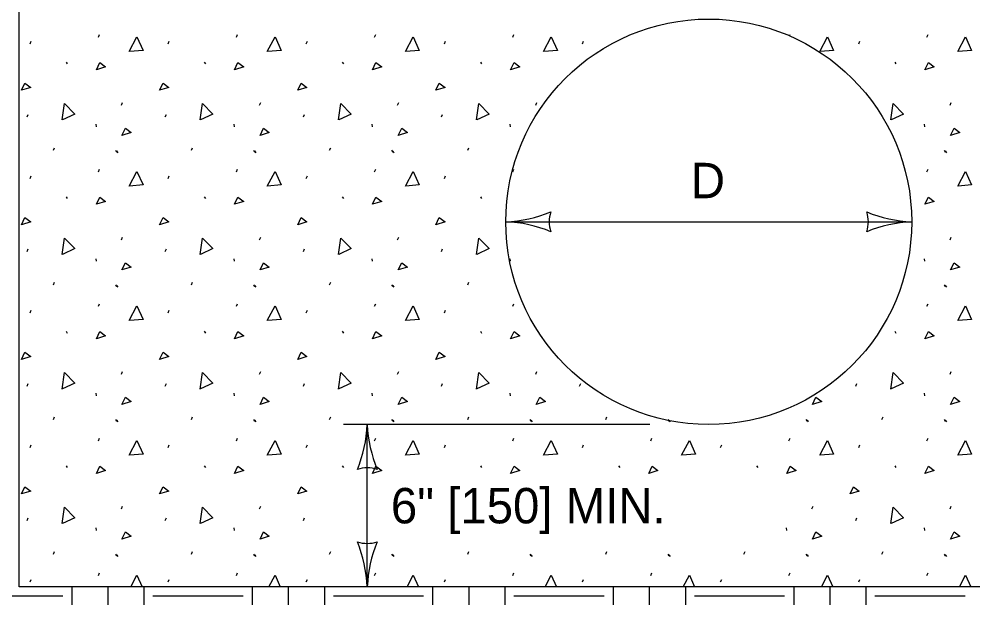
# Model space of a CAD drawing. Extents: x 49991.4 to 50061.4, y 49960.6 to 50011.4.
# Drawn here: x 50012.414 to 50014.03, y 49995.549 to 49996.543 of the extents above; entities that cross this region are included whole.
import ezdxf

# ---------------------------------------------------------------- set-up
doc = ezdxf.new("R2010")
doc.units = 0
for name, color, linetype in [('Level 1', 7, 'Continuous'), ('Level 2', 7, 'Continuous'), ('Level 3', 7, 'Continuous')]:
    doc.layers.add(name, color=color, linetype=linetype)

msp = doc.modelspace()

# ---------------------------------------------------------------- linework, layer by layer
at = {"layer": 'Level 1'}
for p, q in [((50012.4143, 49995.58), (50012.4143, 49997.0926)), ((50012.5487, 49996.5119), (50012.5506, 49996.5163)), ((50012.7826, 49996.5119), (50012.7846, 49996.5163)), ((50013.0166, 49996.5119), (50013.0186, 49996.5163)), ((50013.2506, 49996.5119), (50013.2525, 49996.5163)), ((50013.7194, 49996.514), (50013.7204, 49996.5163)), ((50013.9524, 49996.5119), (50013.9544, 49996.5163)), ((50012.4329, 49996.5007), (50012.4349, 49996.5051)), ((50012.6669, 49996.5007), (50012.6688, 49996.5051)), ((50012.9008, 49996.5007), (50012.9028, 49996.5051)), ((50013.1348, 49996.5007), (50013.1368, 49996.5051)), ((50013.3688, 49996.5007), (50013.3707, 49996.5051)), ((50013.8367, 49996.5007), (50013.8386, 49996.5051)), ((50012.494, 49996.4694), (50012.4959, 49996.4665)), ((50012.7279, 49996.4694), (50012.7299, 49996.4665)), ((50012.9619, 49996.4694), (50012.9639, 49996.4665)), ((50013.1959, 49996.4694), (50013.1978, 49996.4665)), ((50013.8977, 49996.4694), (50013.8997, 49996.4665)), ((50012.5878, 49996.3967), (50012.5897, 49996.4011)), ((50012.8217, 49996.3967), (50012.8237, 49996.4011)), ((50013.0557, 49996.3967), (50013.0576, 49996.4011)), ((50013.2896, 49996.3967), (50013.2916, 49996.4011)), ((50013.9915, 49996.3967), (50013.9935, 49996.4011)), ((50012.4281, 49996.3766), (50012.43, 49996.381)), ((50012.662, 49996.3766), (50012.664, 49996.381)), ((50012.896, 49996.3766), (50012.8979, 49996.381)), ((50013.1299, 49996.3766), (50013.1319, 49996.381)), ((50012.5442, 49996.3644), (50012.5447, 49996.36)), ((50012.7781, 49996.3644), (50012.7786, 49996.36)), ((50013.0121, 49996.3644), (50013.0126, 49996.36)), ((50013.246, 49996.3644), (50013.2465, 49996.36)), ((50013.9479, 49996.3644), (50013.9484, 49996.36)), ((50012.4725, 49996.32), (50012.4744, 49996.3244)), ((50012.7065, 49996.32), (50012.7084, 49996.3244)), ((50012.9404, 49996.32), (50012.9424, 49996.3244)), ((50013.1744, 49996.32), (50013.1763, 49996.3244)), ((50012.5775, 49996.32), (50012.5795, 49996.317)), ((50012.5795, 49996.3189), (50012.5814, 49996.3159)), ((50012.8115, 49996.32), (50012.8134, 49996.317)), ((50012.8134, 49996.3189), (50012.8154, 49996.3159)), ((50013.0454, 49996.32), (50013.0474, 49996.317)), ((50013.0474, 49996.3189), (50013.0493, 49996.3159)), ((50013.9813, 49996.32), (50013.9832, 49996.317)), ((50013.9832, 49996.3189), (50013.9852, 49996.3159)), ((50012.4329, 49996.2725), (50012.4349, 49996.2769)), ((50012.5487, 49996.2838), (50012.5506, 49996.2882)), ((50012.6669, 49996.2725), (50012.6688, 49996.2769)), ((50012.7826, 49996.2838), (50012.7846, 49996.2882)), ((50012.9008, 49996.2725), (50012.9028, 49996.2769)), ((50013.0166, 49996.2838), (50013.0186, 49996.2882)), ((50013.1348, 49996.2725), (50013.1368, 49996.2769)), ((50013.2506, 49996.2838), (50013.2525, 49996.2882)), ((50013.9524, 49996.2838), (50013.9544, 49996.2882)), ((50012.494, 49996.2413), (50012.4959, 49996.2384)), ((50012.7279, 49996.2413), (50012.7299, 49996.2384)), ((50012.9619, 49996.2413), (50012.9639, 49996.2384)), ((50013.1959, 49996.2413), (50013.1978, 49996.2384)), ((50012.5878, 49996.1685), (50012.5897, 49996.1729)), ((50012.8217, 49996.1685), (50012.8237, 49996.1729)), ((50013.0557, 49996.1685), (50013.0576, 49996.1729)), ((50013.9915, 49996.1685), (50013.9935, 49996.1729)), ((50012.4281, 49996.1485), (50012.43, 49996.1529)), ((50012.662, 49996.1485), (50012.664, 49996.1529)), ((50012.896, 49996.1485), (50012.8979, 49996.1529)), ((50013.1299, 49996.1485), (50013.1319, 49996.1529)), ((50012.5442, 49996.1362), (50012.5447, 49996.1318)), ((50012.7781, 49996.1362), (50012.7786, 49996.1318)), ((50013.0121, 49996.1362), (50013.0126, 49996.1318)), ((50013.246, 49996.1362), (50013.2465, 49996.1318)), ((50013.9479, 49996.1362), (50013.9484, 49996.1318)), ((50012.4725, 49996.0918), (50012.4744, 49996.0962)), ((50012.7065, 49996.0918), (50012.7084, 49996.0962)), ((50012.9404, 49996.0918), (50012.9424, 49996.0962)), ((50013.1744, 49996.0918), (50013.1763, 49996.0962)), ((50012.5775, 49996.0918), (50012.5795, 49996.0889)), ((50012.5795, 49996.0907), (50012.5814, 49996.0878)), ((50012.8115, 49996.0918), (50012.8134, 49996.0889)), ((50012.8134, 49996.0907), (50012.8154, 49996.0878)), ((50013.0454, 49996.0918), (50013.0474, 49996.0889)), ((50013.0474, 49996.0907), (50013.0493, 49996.0878)), ((50013.9813, 49996.0918), (50013.9832, 49996.0889)), ((50013.9832, 49996.0907), (50013.9852, 49996.0878)), ((50012.4329, 49996.0444), (50012.4349, 49996.0488)), ((50012.5487, 49996.0556), (50012.5506, 49996.06)), ((50012.6669, 49996.0444), (50012.6688, 49996.0488)), ((50012.7826, 49996.0556), (50012.7846, 49996.06)), ((50012.9008, 49996.0444), (50012.9028, 49996.0488)), ((50013.0166, 49996.0556), (50013.0186, 49996.06)), ((50013.1348, 49996.0444), (50013.1368, 49996.0488)), ((50013.2506, 49996.0556), (50013.2525, 49996.06)), ((50013.9524, 49996.0556), (50013.9544, 49996.06)), ((50012.494, 49996.0131), (50012.4959, 49996.0102)), ((50012.7279, 49996.0131), (50012.7299, 49996.0102)), ((50012.9619, 49996.0131), (50012.9639, 49996.0102)), ((50013.1959, 49996.0131), (50013.1978, 49996.0102)), ((50013.8977, 49996.0131), (50013.8997, 49996.0102)), ((50012.5878, 49995.9404), (50012.5897, 49995.9448)), ((50012.8217, 49995.9404), (50012.8237, 49995.9448)), ((50013.0557, 49995.9404), (50013.0576, 49995.9448)), ((50013.2896, 49995.9404), (50013.2916, 49995.9448)), ((50013.9915, 49995.9404), (50013.9935, 49995.9448)), ((50012.4281, 49995.9203), (50012.43, 49995.9247)), ((50012.662, 49995.9203), (50012.664, 49995.9247)), ((50012.896, 49995.9203), (50012.8979, 49995.9247)), ((50013.1299, 49995.9203), (50013.1319, 49995.9247)), ((50013.3639, 49995.9203), (50013.3658, 49995.9247)), ((50013.8318, 49995.9203), (50013.8337, 49995.9247)), ((50012.5442, 49995.9081), (50012.5447, 49995.9037)), ((50012.7781, 49995.9081), (50012.7786, 49995.9037)), ((50013.0121, 49995.9081), (50013.0126, 49995.9037)), ((50013.246, 49995.9081), (50013.2465, 49995.9037)), ((50013.9479, 49995.9081), (50013.9484, 49995.9037)), ((50012.4725, 49995.8637), (50012.4744, 49995.8681)), ((50012.5775, 49995.8637), (50012.5795, 49995.8608)), ((50012.5795, 49995.8626), (50012.5814, 49995.8596)), ((50012.7065, 49995.8637), (50012.7084, 49995.8681)), ((50012.8115, 49995.8637), (50012.8134, 49995.8608)), ((50012.8134, 49995.8626), (50012.8154, 49995.8596)), ((50012.9404, 49995.8637), (50012.9424, 49995.8681)), ((50013.0454, 49995.8637), (50013.0474, 49995.8608)), ((50013.0474, 49995.8626), (50013.0493, 49995.8596)), ((50013.1744, 49995.8637), (50013.1763, 49995.8681)), ((50013.2794, 49995.8637), (50013.2813, 49995.8608)), ((50013.2813, 49995.8626), (50013.2833, 49995.8596)), ((50013.4083, 49995.8637), (50013.4103, 49995.8681)), ((50013.5133, 49995.8637), (50013.5153, 49995.8608)), ((50013.5153, 49995.8626), (50013.5172, 49995.8596)), ((50013.7473, 49995.8637), (50013.7493, 49995.8608)), ((50013.7493, 49995.8626), (50013.7512, 49995.8596)), ((50013.8762, 49995.8637), (50013.8782, 49995.8681)), ((50013.9813, 49995.8637), (50013.9832, 49995.8608)), ((50013.9832, 49995.8626), (50013.9852, 49995.8596)), ((50012.4329, 49995.8162), (50012.4349, 49995.8206)), ((50012.5487, 49995.8275), (50012.5506, 49995.8319)), ((50012.6669, 49995.8162), (50012.6688, 49995.8206)), ((50012.7826, 49995.8275), (50012.7846, 49995.8319)), ((50012.9008, 49995.8162), (50012.9028, 49995.8206)), ((50013.0166, 49995.8275), (50013.0186, 49995.8319)), ((50013.1348, 49995.8162), (50013.1368, 49995.8206)), ((50013.2506, 49995.8275), (50013.2525, 49995.8319)), ((50013.3688, 49995.8162), (50013.3707, 49995.8206)), ((50013.4845, 49995.8275), (50013.4865, 49995.8319)), ((50013.6027, 49995.8162), (50013.6047, 49995.8206)), ((50013.7185, 49995.8275), (50013.7204, 49995.8319)), ((50013.8367, 49995.8162), (50013.8386, 49995.8206)), ((50013.9524, 49995.8275), (50013.9544, 49995.8319)), ((50012.494, 49995.785), (50012.4959, 49995.7821)), ((50012.7279, 49995.785), (50012.7299, 49995.7821)), ((50012.9619, 49995.785), (50012.9639, 49995.7821)), ((50013.1959, 49995.785), (50013.1978, 49995.7821)), ((50013.4298, 49995.785), (50013.4318, 49995.7821)), ((50013.6638, 49995.785), (50013.6657, 49995.7821)), ((50013.8977, 49995.785), (50013.8997, 49995.7821)), ((50012.5878, 49995.7122), (50012.5897, 49995.7166)), ((50012.8217, 49995.7122), (50012.8237, 49995.7166)), ((50013.7576, 49995.7122), (50013.7595, 49995.7166)), ((50013.9915, 49995.7122), (50013.9935, 49995.7166)), ((50012.4281, 49995.6922), (50012.43, 49995.6966)), ((50012.662, 49995.6922), (50012.664, 49995.6966)), ((50012.896, 49995.6922), (50012.8979, 49995.6966)), ((50013.8318, 49995.6922), (50013.8337, 49995.6966)), ((50012.5442, 49995.6799), (50012.5447, 49995.6755)), ((50012.7781, 49995.6799), (50012.7786, 49995.6755)), ((50013.714, 49995.6799), (50013.7144, 49995.6755)), ((50013.9479, 49995.6799), (50013.9484, 49995.6755)), ((50012.4725, 49995.6355), (50012.4744, 49995.6399)), ((50012.5775, 49995.6355), (50012.5795, 49995.6326)), ((50012.5795, 49995.6344), (50012.5814, 49995.6315)), ((50012.7065, 49995.6355), (50012.7084, 49995.6399)), ((50012.8115, 49995.6355), (50012.8134, 49995.6326)), ((50012.8134, 49995.6344), (50012.8154, 49995.6315)), ((50012.9404, 49995.6355), (50012.9424, 49995.6399)), ((50013.0454, 49995.6355), (50013.0474, 49995.6326)), ((50013.0474, 49995.6344), (50013.0493, 49995.6315)), ((50013.1744, 49995.6355), (50013.1763, 49995.6399)), ((50013.2794, 49995.6355), (50013.2813, 49995.6326)), ((50013.2813, 49995.6344), (50013.2833, 49995.6315)), ((50013.4083, 49995.6355), (50013.4103, 49995.6399)), ((50013.5133, 49995.6355), (50013.5153, 49995.6326)), ((50013.5153, 49995.6344), (50013.5172, 49995.6315)), ((50013.6423, 49995.6355), (50013.6442, 49995.6399)), ((50013.7473, 49995.6355), (50013.7493, 49995.6326)), ((50013.7493, 49995.6344), (50013.7512, 49995.6315)), ((50013.8762, 49995.6355), (50013.8782, 49995.6399)), ((50013.9813, 49995.6355), (50013.9832, 49995.6326)), ((50013.9832, 49995.6344), (50013.9852, 49995.6315)), ((50012.5487, 49995.5993), (50012.5506, 49995.6037)), ((50012.7826, 49995.5993), (50012.7846, 49995.6037)), ((50013.0166, 49995.5993), (50013.0186, 49995.6037)), ((50013.2506, 49995.5993), (50013.2525, 49995.6037)), ((50013.4845, 49995.5993), (50013.4865, 49995.6037)), ((50013.7185, 49995.5993), (50013.7204, 49995.6037)), ((50013.9524, 49995.5993), (50013.9544, 49995.6037)), ((50014.7511, 49995.58), (50012.4143, 49995.58)), ((50012.4329, 49995.5881), (50012.4349, 49995.5925)), ((50012.5035, 49995.58), (50012.5035, 49995.5492)), ((50012.5647, 49995.58), (50012.5647, 49995.5492)), ((50012.6258, 49995.58), (50012.6258, 49995.5492)), ((50012.6669, 49995.5881), (50012.6688, 49995.5925)), ((50012.8093, 49995.58), (50012.8093, 49995.5492)), ((50012.8704, 49995.58), (50012.8704, 49995.5492)), ((50012.9008, 49995.5881), (50012.9028, 49995.5925)), ((50012.9316, 49995.58), (50012.9316, 49995.5492)), ((50013.5484, 49995.58), (50012.9699, 49995.58)), ((50013.115, 49995.58), (50013.115, 49995.5492)), ((50013.1348, 49995.5881), (50013.1368, 49995.5925)), ((50013.1762, 49995.58), (50013.1762, 49995.5492)), ((50013.2373, 49995.58), (50013.2373, 49995.5492)), ((50013.3688, 49995.5881), (50013.3707, 49995.5925)), ((50013.4208, 49995.58), (50013.4208, 49995.5492)), ((50013.482, 49995.58), (50013.482, 49995.5492)), ((50013.5431, 49995.58), (50013.5431, 49995.5492)), ((50013.6027, 49995.5881), (50013.6047, 49995.5925)), ((50013.7266, 49995.58), (50013.7266, 49995.5492)), ((50013.7877, 49995.58), (50013.7877, 49995.5492)), ((50013.8367, 49995.5881), (50013.8386, 49995.5925)), ((50013.8489, 49995.58), (50013.8489, 49995.5492)), ((50012.3353, 49995.5645), (50012.4882, 49995.5645)), ((50012.6411, 49995.5645), (50012.794, 49995.5645)), ((50012.9469, 49995.5645), (50013.0997, 49995.5645)), ((50013.2526, 49995.5645), (50013.4055, 49995.5645)), ((50013.5584, 49995.5645), (50013.7113, 49995.5645)), ((50013.8642, 49995.5645), (50014.017, 49995.5645))]:
    msp.add_line(p, q, dxfattribs=at)
for points in [[(50012.601, 49996.4875), (50012.6141, 49996.5124), (50012.6244, 49996.4895), (50012.6014, 49996.4875)], [(50012.8349, 49996.4875), (50012.8481, 49996.5124), (50012.8584, 49996.4895), (50012.8354, 49996.4875)], [(50013.0689, 49996.4875), (50013.0821, 49996.5124), (50013.0923, 49996.4895), (50013.0694, 49996.4875)], [(50013.3028, 49996.4875), (50013.316, 49996.5124), (50013.3263, 49996.4895), (50013.3033, 49996.4875)], [(50013.7707, 49996.4875), (50013.7839, 49996.5124), (50013.7942, 49996.4895), (50013.7712, 49996.4875)], [(50014.0047, 49996.4875), (50014.0179, 49996.5124), (50014.0281, 49996.4895), (50014.0052, 49996.4875)], [(50012.5453, 49996.4567), (50012.5511, 49996.4689), (50012.5609, 49996.4616), (50012.5453, 49996.4567)], [(50012.7792, 49996.4567), (50012.7851, 49996.4689), (50012.7949, 49996.4616), (50012.7792, 49996.4567)], [(50013.0132, 49996.4567), (50013.019, 49996.4689), (50013.0288, 49996.4616), (50013.0132, 49996.4567)], [(50013.2471, 49996.4567), (50013.253, 49996.4689), (50013.2628, 49996.4616), (50013.2471, 49996.4567)], [(50013.949, 49996.4567), (50013.9549, 49996.4689), (50013.9646, 49996.4616), (50013.949, 49996.4567)], [(50012.4184, 49996.4218), (50012.4242, 49996.434), (50012.434, 49996.4267), (50012.4184, 49996.4218)], [(50012.6523, 49996.4218), (50012.6582, 49996.434), (50012.668, 49996.4267), (50012.6523, 49996.4218)], [(50012.8863, 49996.4218), (50012.8922, 49996.434), (50012.9019, 49996.4267), (50012.8863, 49996.4218)], [(50013.1203, 49996.4218), (50013.1261, 49996.434), (50013.1359, 49996.4267), (50013.1203, 49996.4218)], [(50012.4875, 49996.3716), (50012.4913, 49996.3995), (50012.5088, 49996.3814), (50012.4879, 49996.3717)], [(50012.7214, 49996.3716), (50012.7253, 49996.3995), (50012.7428, 49996.3814), (50012.7219, 49996.3717)], [(50012.9554, 49996.3716), (50012.9593, 49996.3995), (50012.9767, 49996.3814), (50012.9558, 49996.3717)], [(50013.1893, 49996.3716), (50013.1932, 49996.3995), (50013.2107, 49996.3814), (50013.1898, 49996.3717)], [(50013.8912, 49996.3716), (50013.8951, 49996.3995), (50013.9126, 49996.3814), (50013.8917, 49996.3717)], [(50012.5887, 49996.3454), (50012.5946, 49996.3576), (50012.6044, 49996.3503), (50012.5887, 49996.3454)], [(50012.8227, 49996.3454), (50012.8286, 49996.3576), (50012.8383, 49996.3503), (50012.8227, 49996.3454)], [(50013.0567, 49996.3454), (50013.0625, 49996.3576), (50013.0723, 49996.3503), (50013.0567, 49996.3454)], [(50013.9925, 49996.3454), (50013.9984, 49996.3576), (50014.0081, 49996.3503), (50013.9925, 49996.3454)], [(50012.601, 49996.2594), (50012.6141, 49996.2843), (50012.6244, 49996.2613), (50012.6014, 49996.2594)], [(50012.8349, 49996.2594), (50012.8481, 49996.2843), (50012.8584, 49996.2613), (50012.8354, 49996.2594)], [(50013.0689, 49996.2594), (50013.0821, 49996.2843), (50013.0923, 49996.2613), (50013.0694, 49996.2594)], [(50014.0047, 49996.2594), (50014.0179, 49996.2843), (50014.0281, 49996.2613), (50014.0052, 49996.2594)], [(50012.5453, 49996.2286), (50012.5511, 49996.2408), (50012.5609, 49996.2335), (50012.5453, 49996.2286)], [(50012.7792, 49996.2286), (50012.7851, 49996.2408), (50012.7949, 49996.2335), (50012.7792, 49996.2286)], [(50013.0132, 49996.2286), (50013.019, 49996.2408), (50013.0288, 49996.2335), (50013.0132, 49996.2286)], [(50013.949, 49996.2286), (50013.9549, 49996.2408), (50013.9646, 49996.2335), (50013.949, 49996.2286)], [(50012.4184, 49996.1937), (50012.4242, 49996.2059), (50012.434, 49996.1986), (50012.4184, 49996.1937)], [(50012.6523, 49996.1937), (50012.6582, 49996.2059), (50012.668, 49996.1986), (50012.6523, 49996.1937)], [(50012.8863, 49996.1937), (50012.8922, 49996.2059), (50012.9019, 49996.1986), (50012.8863, 49996.1937)], [(50013.1203, 49996.1937), (50013.1261, 49996.2059), (50013.1359, 49996.1986), (50013.1203, 49996.1937)], [(50012.4875, 49996.1434), (50012.4913, 49996.1713), (50012.5088, 49996.1533), (50012.4879, 49996.1436)], [(50012.7214, 49996.1434), (50012.7253, 49996.1713), (50012.7428, 49996.1533), (50012.7219, 49996.1436)], [(50012.9554, 49996.1434), (50012.9593, 49996.1713), (50012.9767, 49996.1533), (50012.9558, 49996.1436)], [(50013.1893, 49996.1434), (50013.1932, 49996.1713), (50013.2107, 49996.1533), (50013.1898, 49996.1436)], [(50012.5887, 49996.1172), (50012.5946, 49996.1294), (50012.6044, 49996.1221), (50012.5887, 49996.1172)], [(50012.8227, 49996.1172), (50012.8286, 49996.1294), (50012.8383, 49996.1221), (50012.8227, 49996.1172)], [(50013.0567, 49996.1172), (50013.0625, 49996.1294), (50013.0723, 49996.1221), (50013.0567, 49996.1172)], [(50013.9925, 49996.1172), (50013.9984, 49996.1294), (50014.0081, 49996.1221), (50013.9925, 49996.1172)], [(50012.601, 49996.0312), (50012.6141, 49996.0561), (50012.6244, 49996.0332), (50012.6014, 49996.0312)], [(50012.8349, 49996.0312), (50012.8481, 49996.0561), (50012.8584, 49996.0332), (50012.8354, 49996.0312)], [(50013.0689, 49996.0312), (50013.0821, 49996.0561), (50013.0923, 49996.0332), (50013.0694, 49996.0312)], [(50014.0047, 49996.0312), (50014.0179, 49996.0561), (50014.0281, 49996.0332), (50014.0052, 49996.0312)], [(50012.5453, 49996.0004), (50012.5511, 49996.0126), (50012.5609, 49996.0053), (50012.5453, 49996.0004)], [(50012.7792, 49996.0004), (50012.7851, 49996.0126), (50012.7949, 49996.0053), (50012.7792, 49996.0004)], [(50013.0132, 49996.0004), (50013.019, 49996.0126), (50013.0288, 49996.0053), (50013.0132, 49996.0004)], [(50013.2471, 49996.0004), (50013.253, 49996.0126), (50013.2628, 49996.0053), (50013.2471, 49996.0004)], [(50013.949, 49996.0004), (50013.9549, 49996.0126), (50013.9646, 49996.0053), (50013.949, 49996.0004)], [(50012.4184, 49995.9655), (50012.4242, 49995.9777), (50012.434, 49995.9704), (50012.4184, 49995.9655)], [(50012.6523, 49995.9655), (50012.6582, 49995.9777), (50012.668, 49995.9704), (50012.6523, 49995.9655)], [(50012.8863, 49995.9655), (50012.8922, 49995.9777), (50012.9019, 49995.9704), (50012.8863, 49995.9655)], [(50013.1203, 49995.9655), (50013.1261, 49995.9777), (50013.1359, 49995.9704), (50013.1203, 49995.9655)], [(50013.8378, 49995.9704), (50013.8374, 49995.9703)], [(50012.4875, 49995.9153), (50012.4913, 49995.9432), (50012.5088, 49995.9251), (50012.4879, 49995.9154)], [(50012.7214, 49995.9153), (50012.7253, 49995.9432), (50012.7428, 49995.9251), (50012.7219, 49995.9154)], [(50012.9554, 49995.9153), (50012.9593, 49995.9432), (50012.9767, 49995.9251), (50012.9558, 49995.9154)], [(50013.1893, 49995.9153), (50013.1932, 49995.9432), (50013.2107, 49995.9251), (50013.1898, 49995.9154)], [(50013.8912, 49995.9153), (50013.8951, 49995.9432), (50013.9126, 49995.9251), (50013.8917, 49995.9154)], [(50012.5887, 49995.8891), (50012.5946, 49995.9013), (50012.6044, 49995.894), (50012.5887, 49995.8891)], [(50012.8227, 49995.8891), (50012.8286, 49995.9013), (50012.8383, 49995.894), (50012.8227, 49995.8891)], [(50013.0567, 49995.8891), (50013.0625, 49995.9013), (50013.0723, 49995.894), (50013.0567, 49995.8891)], [(50013.2906, 49995.8891), (50013.2965, 49995.9013), (50013.3062, 49995.894), (50013.2906, 49995.8891)], [(50013.7585, 49995.8891), (50013.7644, 49995.9013), (50013.7742, 49995.894), (50013.7585, 49995.8891)], [(50013.9925, 49995.8891), (50013.9984, 49995.9013), (50014.0081, 49995.894), (50013.9925, 49995.8891)], [(50012.601, 49995.8031), (50012.6141, 49995.828), (50012.6244, 49995.805), (50012.6014, 49995.8031)], [(50012.8349, 49995.8031), (50012.8481, 49995.828), (50012.8584, 49995.805), (50012.8354, 49995.8031)], [(50013.0689, 49995.8031), (50013.0821, 49995.828), (50013.0923, 49995.805), (50013.0694, 49995.8031)], [(50013.3028, 49995.8031), (50013.316, 49995.828), (50013.3263, 49995.805), (50013.3033, 49995.8031)], [(50013.5368, 49995.8031), (50013.55, 49995.828), (50013.5602, 49995.805), (50013.5373, 49995.8031)], [(50013.7707, 49995.8031), (50013.7839, 49995.828), (50013.7942, 49995.805), (50013.7712, 49995.8031)], [(50014.0047, 49995.8031), (50014.0179, 49995.828), (50014.0281, 49995.805), (50014.0052, 49995.8031)], [(50012.5453, 49995.7723), (50012.5511, 49995.7845), (50012.5609, 49995.7772), (50012.5453, 49995.7723)], [(50012.7792, 49995.7723), (50012.7851, 49995.7845), (50012.7949, 49995.7772), (50012.7792, 49995.7723)], [(50013.0132, 49995.7723), (50013.019, 49995.7845), (50013.0288, 49995.7772), (50013.0132, 49995.7723)], [(50013.2471, 49995.7723), (50013.253, 49995.7845), (50013.2628, 49995.7772), (50013.2471, 49995.7723)], [(50013.4811, 49995.7723), (50013.487, 49995.7845), (50013.4967, 49995.7772), (50013.4811, 49995.7723)], [(50013.7151, 49995.7723), (50013.7209, 49995.7845), (50013.7307, 49995.7772), (50013.7151, 49995.7723)], [(50013.949, 49995.7723), (50013.9549, 49995.7845), (50013.9646, 49995.7772), (50013.949, 49995.7723)], [(50012.4184, 49995.7374), (50012.4242, 49995.7496), (50012.434, 49995.7423), (50012.4184, 49995.7374)], [(50012.6523, 49995.7374), (50012.6582, 49995.7496), (50012.668, 49995.7423), (50012.6523, 49995.7374)], [(50012.8863, 49995.7374), (50012.8922, 49995.7496), (50012.9019, 49995.7423), (50012.8863, 49995.7374)], [(50013.8221, 49995.7374), (50013.828, 49995.7496), (50013.8378, 49995.7423), (50013.8221, 49995.7374)], [(50012.4875, 49995.6871), (50012.4913, 49995.7151), (50012.5088, 49995.697), (50012.4879, 49995.6873)], [(50012.7214, 49995.6871), (50012.7253, 49995.7151), (50012.7428, 49995.697), (50012.7219, 49995.6873)], [(50013.8912, 49995.6871), (50013.8951, 49995.7151), (50013.9126, 49995.697), (50013.8917, 49995.6873)], [(50012.5887, 49995.6609), (50012.5946, 49995.6731), (50012.6044, 49995.6658), (50012.5887, 49995.6609)], [(50012.8227, 49995.6609), (50012.8286, 49995.6731), (50012.8383, 49995.6658), (50012.8227, 49995.6609)], [(50013.7585, 49995.6609), (50013.7644, 49995.6731), (50013.7742, 49995.6658), (50013.7585, 49995.6609)], [(50013.9925, 49995.6609), (50013.9984, 49995.6731), (50014.0081, 49995.6658), (50013.9925, 49995.6609)], [(50012.6037, 49995.58), (50012.6141, 49995.5998), (50012.623, 49995.58)], [(50012.8376, 49995.58), (50012.8481, 49995.5998), (50012.8569, 49995.58)], [(50013.0716, 49995.58), (50013.0821, 49995.5998), (50013.0909, 49995.58)], [(50013.3055, 49995.58), (50013.316, 49995.5998), (50013.3249, 49995.58)], [(50013.5395, 49995.58), (50013.55, 49995.5998), (50013.5588, 49995.58)], [(50013.7735, 49995.58), (50013.7839, 49995.5998), (50013.7928, 49995.58)], [(50014.0074, 49995.58), (50014.0179, 49995.5998), (50014.0267, 49995.58)]]:
    msp.add_lwpolyline(points, dxfattribs=at)
msp.add_circle((50013.5827, 49996.1988), 0.3438, dxfattribs=at)
at = {"layer": 'Level 3'}
for p, q in [((50013.239, 49996.1988), (50013.9265, 49996.1988)), ((50013.4827, 49995.855), (50012.9642, 49995.855)), ((50013.0042, 49995.58), (50013.0042, 49995.855))]:
    msp.add_line(p, q, dxfattribs=at)
for centre, radius, start, end in [((50013.2275, 49996.4315), 0.233, 272.8273, 292.0772), ((50013.3672, 49996.1988), 0.0548, 162.1388, 197.8612), ((50013.9357, 49996.4209), 0.2223, 247.456, 267.6395), ((50013.7983, 49996.1988), 0.0548, 342.1388, 17.8612), ((50013.2298, 49995.9767), 0.2223, 67.456, 87.6395), ((50013.938, 49995.9661), 0.233, 92.8273, 112.0772), ((50012.7821, 49995.8642), 0.2223, 337.456, 357.6395), ((50013.2369, 49995.8665), 0.233, 182.8273, 202.0772), ((50013.0042, 49995.7268), 0.0548, 72.1388, 107.8612), ((50013.0042, 49995.7083), 0.0548, 252.1388, 287.8612), ((50012.7715, 49995.5685), 0.233, 2.8273, 22.0772), ((50013.2264, 49995.5709), 0.2223, 157.456, 177.6395)]:
    msp.add_arc(centre, radius, start, end, dxfattribs=at)

# ---------------------------------------------------------------- texts
at = {"layer": 'Level 2'}
msp.add_text('D', height=0.06, rotation=360, dxfattribs=at).set_placement((50013.5524, 49996.2388))
msp.add_text('6" [150] MIN.', height=0.06, dxfattribs=at).set_placement((50013.0442, 49995.6875))

doc.saveas('drawing.dxf')
